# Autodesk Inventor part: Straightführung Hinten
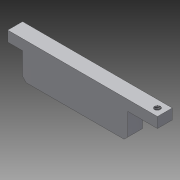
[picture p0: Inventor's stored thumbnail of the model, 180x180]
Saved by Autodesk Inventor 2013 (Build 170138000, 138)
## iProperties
Created: 2012-07
Part Number: Straightführung Hinten
Material: PC/ABS-Kunststoff
Document SubType Name: Modeling
Designer: rYan
Mass: 1.71668 g
Surface Area: 10.6623 cm^2
Volume: 1.14982 cm^3
Density: 1.493 g/cm^3
Author: rYan
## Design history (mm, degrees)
sketch "Skizze1"
  geometry: L1 (-14.2, 0)-(14.2, 0); L2 (14.2, 0)-(14.2, 7); L3 (5.152, 9.8)-(-14.2, 9.8); L4 (-14.2, 7)-(-14.2, 0); L5 (5.152, 9.8)-(18.2, 9.8); L6 (18.2, 9.8)-(18.2, 7); L7 (18.2, 7)-(14.2, 7); L8 (-14.2, 9.8)-(-22.2, 9.8); L9 (-22.2, 9.8)-(-22.2, 7); L10 (-22.2, 7)-(-14.2, 7); L11 (0, -1.96)-(0, 11.76) reference; L12 (-30.28, 0)-(26.28, 0) reference; 1 further point
  constraints: 20 end point, 4 parallel, 3 horizontal, 3 perpendicular, 1 collinear, 2 other
  dimensions: "d0" = 8 distance of L9.end L4.start; "d2" = 28.4 distance of L1.start L1.end; "d3" = 7 distance of L1.end L2.end; "d4" = 9.8 distance between parallel lines of L1 L5; "d15" = 4 distance of L6.end L2.end
extrude "Extrusion1" new body sketch "Skizze1" distance "d5" = 4; taper "d6" = 0 deg
sketch "Skizze2"
  geometry: L1 (0, 0)-(40.4, 0) reference; L2 (40.4, 0)-(40.4, 4) reference; L3 (0, 4)-(40.4, 4) reference; L4 (0, 0)-(0, 4) reference; L5 (0, 2)-(40.4, 2); 2 further points
  constraints: 2 end point, 2 midpoint, 1 point on line
  dimensions: "d16" = 2 distance from line of L2 point (38.4, 2)
hole "Bohrung1" sketch "Skizze2" at (38.4, 2) diameter "d8" = 1.567; stored, may be unused: countersink angle "d12" = 90 deg, drill point angle "d14" = 118 deg; dims "d9" = 6, "d10" = 4, "d11" = 2, "d13" = 4.5
sketch "Skizze3"
  geometry: L1 (28.4, 0)-(28.4, 4) reference; L2 (0, 4)-(28.4, 4) reference; L3 (0, 0)-(0, 4) reference; L4 (0, 0)-(28.4, 0) reference; L5 (28.4, 0)-(28.4, 4) reference; L6 (4.2, 2)-(24.2, 2); L7 (0, 2)-(28.4, 2); L8 (14.2, 4)-(14.2, 0)
  constraints: 6 end point, 3 midpoint, 2 perpendicular, 1 point on line, 1 symmetric about line
  dimensions: "d17" = 20 distance of L6.end L6.start
hole "Bohrung2" sketch "Skizze3" at (4.2, 2), (24.2, 2) diameter "d20" = 2.013; stored, may be unused: countersink angle "d24" = 90 deg, drill point angle "d26" = 118 deg; dims "d21" = 6, "d22" = 4, "d23" = 2, "d25" = 6
chamfer "Fase1" distance "d33" = 1; stored, may be unused: second distance "d34" = 2, angle "d35" = 45 deg
node "Volumenkörper1"
node "Projizierte Kontur1"
node "Projizierte Kontur2"
